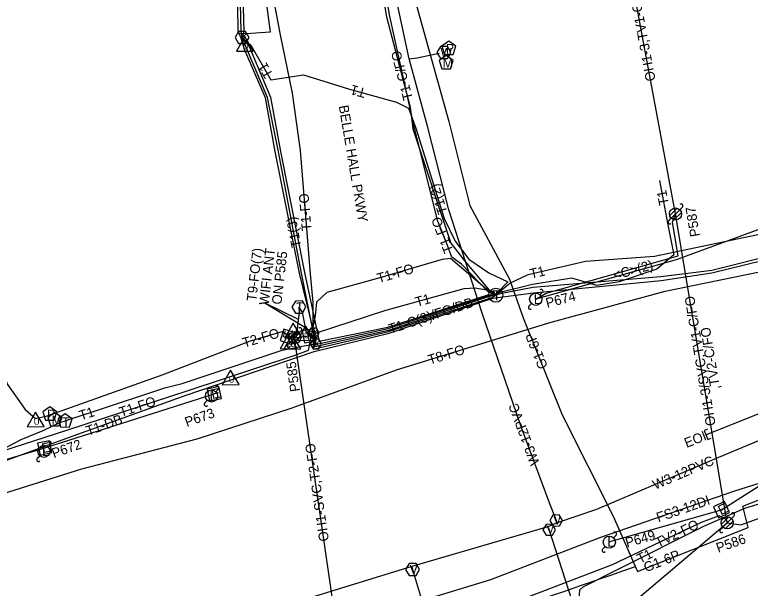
# Model space of a CAD drawing. Extents: x 2336688 to 2352634, y 362473 to 369571.
# Drawn here: x 2350284.9 to 2350587.4, y 368425.3 to 368661.2 of the extents above; entities that cross this region are included whole.
import ezdxf

# ---------------------------------------------------------------- set-up
doc = ezdxf.new("R2010")
doc.units = 0
for name, color, linetype in [('RD_EX_DV_Prop', 7, 'Continuous'), ('RD_EX_DV_TX_Prop', 7, 'Continuous'), ('RD_EX_RW', 7, 'Continuous'), ('RD_EX_RW_TX', 7, 'Continuous'), ('RD_HC_CL_Rel', 7, 'Continuous'), ('RD_HC_Data_Tic', 7, 'Continuous'), ('RD_PD_CstnLmt', 7, 'Continuous'), ('RD_PD_Final_TrvlWay', 7, 'Continuous'), ('RD_PD_PatLn2', 7, 'Continuous'), ('RD_PD_PatLn3', 7, 'Continuous'), ('RD_PD_PatLn4', 7, 'Continuous'), ('RD_SHT_ShtClip', 7, 'Continuous'), ('RD_Sketch1', 7, 'Continuous'), ('RD_Sketch2', 7, 'Continuous'), ('RD_Sketch5', 7, 'Continuous'), ('RD_TX_Misc1', 7, 'Continuous')]:
    doc.layers.add(name, color=color, linetype=linetype)

msp = doc.modelspace()

# ---------------------------------------------------------------- linework, layer by layer
at = {"layer": 'RD_EX_RW'}
for q in [(2350404.43, 368532.56), (2350401.5, 368535.99)]:
    msp.add_line((2350387.42, 368542.82), q, dxfattribs=at)
at = {"layer": 'RD_EX_RW_TX'}
for points in [[(2350388.75, 369009.97), (2350397.22, 368958.18), (2350404.87, 368909.74), (2350411.62, 368859.62), (2350417.85, 368811.58), (2350423.06, 368763.6), (2350429.71, 368713.05), (2350437.68, 368660.97), (2350447.52, 368623.27), (2350448.62, 368614.36), (2350464.25, 368567.26), (2350469.96, 368559.91), (2350480.07, 368547.98), (2350481.76, 368547.21), (2350482.64, 368545.94)], [(2350482.64, 368545.94), (2350481.31, 368546.91), (2350479.8, 368547.15), (2350468.6, 368558.68), (2350464.62, 368561.57), (2350462.94, 368566.31), (2350458.88, 368576.34), (2350449.26, 368614.59), (2350439.06, 368661.24), (2350430.47, 368713.16), (2350424.26, 368763.63), (2350419.63, 368812.07), (2350412.7, 368859.94), (2350405.88, 368909.92), (2350398.4, 368958.42), (2350390.1, 369010.31)], [(2350326.28, 369000.12), (2350332.79, 368954.21), (2350348.71, 368900.79), (2350357.27, 368854.35), (2350367.98, 368802.75), (2350376.91, 368753.55), (2350383.44, 368712.71), (2350383.88, 368703.63), (2350378.08, 368694.65), (2350379.09, 368654.23), (2350378.39, 368651.86), (2350381.3, 368648.18), (2350390.15, 368627.39), (2350394.17, 368604.93), (2350404.13, 368555.18), (2350410.09, 368526.92), (2350438.39, 368532.65), (2350479.49, 368546), (2350481.06, 368546.18), (2350482.64, 368545.94)], [(2350408.75, 368525.77), (2350408.57, 368526.1), (2350402.78, 368554.87), (2350393.43, 368604.85), (2350388.81, 368627.14), (2350380.28, 368647.53), (2350378.39, 368651.86), (2350378.01, 368654.34), (2350377.12, 368694.93), (2350382.9, 368704.01), (2350382.6, 368712.47), (2350374.83, 368753.42), (2350364.37, 368802.15), (2350353.94, 368853.94), (2350343.54, 368900.46), (2350334.62, 368932.93), (2350327.82, 368949.81), (2350315.54, 368963), (2350294.55, 368977.59)], [(2350171.87, 368427.87), (2350217.94, 368444.86), (2350264.95, 368459.5), (2350312.55, 368474.5), (2350359.96, 368486.74), (2350398.97, 368499.58), (2350441.96, 368515.14), (2350504.54, 368534.47), (2350552.41, 368547.56), (2350602.53, 368557.75), (2350651.32, 368575.57), (2350695.05, 368595.12), (2350743.66, 368609.85), (2350789.93, 368626.9), (2350839.13, 368641.87), (2350884.51, 368658.74), (2350931.21, 368675.96), (2350977.7, 368689.48), (2351026.67, 368705.73), (2351072.69, 368726.31)], [(2350550.06, 368593.04), (2350553.4, 368575.51), (2350556.04, 368562.41), (2350549.03, 368556.57), (2350533.44, 368551.33), (2350524.3, 368549.87), (2350514.04, 368552.9), (2350497.9, 368550.25), (2350484.03, 368546.87), (2350482.64, 368545.94), (2350481.02, 368545.5), (2350479.63, 368545.14), (2350438.63, 368531.39), (2350408.36, 368524.65), (2350407.99, 368526.73), (2350407.79, 368529.35), (2350407.84, 368530.28), (2350407.93, 368530.85), (2350401.96, 368554.87), (2350391.98, 368604.93), (2350387.98, 368627), (2350379.43, 368646.93), (2350378.07, 368651.64), (2350376.74, 368654.45), (2350376.28, 368695.46)], [(2350386.33, 368681.11), (2350389.94, 368654.04), (2350380.03, 368653.44), (2350378.39, 368651.86), (2350382.02, 368648.71), (2350390.17, 368634.44), (2350403.61, 368636.52), (2350422.61, 368630.68), (2350441.9, 368625.3), (2350446.8, 368622.86), (2350449.89, 368614.63), (2350461.49, 368577.44), (2350466.02, 368568.14), (2350471.7, 368560.62), (2350479.9, 368555.07), (2350487.67, 368551.3), (2350483.53, 368547.05), (2350482.64, 368545.94)], [(2350388.65, 368681.34), (2350394.12, 368653.01), (2350399.06, 368628.98), (2350402.27, 368605.42), (2350406.43, 368554.68), (2350407.49, 368542.86), (2350407.54, 368537.76), (2350407.61, 368523.66), (2350438.65, 368530.88), (2350479.91, 368544.49), (2350481.3, 368544.93), (2350482.64, 368545.94)], [(2350275.43, 368480.16), (2350287.53, 368486.53), (2350296.58, 368490.27), (2350303.41, 368493.47), (2350305.37, 368494.05), (2350307.12, 368494.79), (2350317.72, 368498.2), (2350346.6, 368507.79), (2350353.81, 368509.54), (2350394.92, 368523.3), (2350407.49, 368525.69), (2350408.75, 368525.77), (2350410.33, 368525.94), (2350438.45, 368532.21), (2350479.57, 368545.7), (2350481.03, 368545.75), (2350482.64, 368545.94), (2350483.89, 368546.96), (2350488.5, 368550.84), (2350496.07, 368554.39), (2350519.66, 368559.91), (2350547.98, 368561.97), (2350596.49, 368572.11)], [(2350078.43, 368410.11), (2350121.57, 368423.4), (2350143.91, 368430.19), (2350168.83, 368437.37), (2350214.23, 368453.99), (2350261.28, 368470.53), (2350307.48, 368487.5), (2350354.97, 368504.62), (2350408.06, 368522.73), (2350438.94, 368530.22), (2350481.48, 368544.67), (2350498.27, 368546.89), (2350550.8, 368551.91), (2350571.6, 368555.09), (2350599.59, 368561.91)], [(2350599.46, 368563.03), (2350571.6, 368556.05), (2350550.59, 368553.36), (2350498.04, 368549.07), (2350484.48, 368546.36), (2350482.64, 368545.94), (2350481.12, 368546.45), (2350467.8, 368557.82), (2350464.13, 368560.91), (2350460.65, 368560.51), (2350435.07, 368553), (2350413.22, 368546.93), (2350409.03, 368543.01), (2350408.48, 368537.37), (2350405.62, 368523.15), (2350399.7, 368520.91), (2350356.09, 368506.55), (2350306.59, 368490.37), (2350279.1, 368481.38), (2350264.89, 368477.05), (2350263.31, 368482.45), (2350263.08, 368483.91)], [(2350482.64, 368545.94), (2350481.66, 368546.86), (2350479.7, 368547.74), (2350474.3, 368548.82), (2350469.57, 368548.46), (2350437, 368539.4), (2350408.92, 368530.22), (2350407.84, 368530.28)], [(2350272, 368534.04), (2350281.85, 368509.07), (2350289.13, 368498.91), (2350293.42, 368495.17), (2350298.29, 368496.27), (2350346, 368513.18), (2350381.9, 368527.1), (2350394.9, 368530.89), (2350398.81, 368528.45), (2350399.92, 368528.37), (2350406.03, 368529.13), (2350404.87, 368530.3), (2350403.18, 368538.96), (2350401.8, 368540.99), (2350401.84, 368538.95), (2350400.7, 368528.92), (2350400.64, 368528.58), (2350399.92, 368528.37)], [(2350438.31, 368353.14), (2350443.06, 368361.29), (2350461.37, 368365.85), (2350472.57, 368367.45), (2350475.55, 368368.48), (2350473.81, 368381.16), (2350466.45, 368400.79), (2350465.63, 368402.3), (2350467.73, 368402.72), (2350477.74, 368405.85), (2350509.1, 368415.22), (2350517.8, 368417.58), (2350517.14, 368422.45), (2350517.32, 368424.65), (2350518.71, 368425.94), (2350533.4, 368433.24), (2350568.35, 368450.8), (2350585.17, 368458.19), (2350631.55, 368472.55)], [(2350577.9, 368452.24), (2350577.71, 368453.44), (2350574.65, 368455.11), (2350567.18, 368452.41), (2350530.66, 368434.99), (2350490.17, 368419.45), (2350440.7, 368401.32), (2350389.67, 368387.65), (2350345.03, 368375.16), (2350304.59, 368361.14), (2350291.95, 368359.89), (2350248.07, 368344.34), (2350203.54, 368331.65), (2350161.47, 368317.74), (2350118.87, 368303.47)]]:
    msp.add_lwpolyline(points, dxfattribs=at)
for points in [[(2350381.28, 368651.86), (2350379.83, 368654.36), (2350376.95, 368654.36), (2350375.5, 368651.86), (2350376.95, 368649.36), (2350379.83, 368649.36)], [(2350404.68, 368541.03), (2350403.21, 368543.51), (2350400.32, 368543.47), (2350398.91, 368540.95), (2350400.39, 368538.47), (2350403.27, 368538.51)], [(2350408.05, 368532.04), (2350403.13, 368531.15), (2350404.01, 368526.23), (2350408.93, 368527.11)], [(2350410.14, 368530.28), (2350408.99, 368532.28), (2350406.68, 368532.28), (2350405.53, 368530.28), (2350406.68, 368528.28), (2350408.99, 368528.28)], [(2350411.06, 368525.77), (2350409.91, 368527.77), (2350407.6, 368527.77), (2350406.44, 368525.77), (2350407.6, 368523.77), (2350409.91, 368523.77)], [(2350305.6, 368497.08), (2350302.78, 368494.96), (2350303.91, 368491.63), (2350307.44, 368491.67), (2350308.48, 368495.04)]]:
    msp.add_lwpolyline(points, close=True, dxfattribs=at)
msp.add_circle((2350482.74, 368545.84), 2.89, dxfattribs=at)
at = {"layer": 'RD_HC_CL_Rel'}
msp.add_lwpolyline([(2350393.46, 369009.48), (2350402.47, 368959.36), (2350407.9, 368910.71), (2350415.61, 368860.55), (2350423.26, 368811.96), (2350431.46, 368765.12), (2350440.2, 368714.98), (2350450.17, 368665.06), (2350463.37, 368617.29), (2350472.09, 368582.73), (2350488.34, 368552.4), (2350494.02, 368536.52), (2350510.05, 368496.62), (2350530.98, 368454.93), (2350541.05, 368432.24), (2350586.57, 368450.28), (2350584.33, 368459.13), (2350630.35, 368477.17)], dxfattribs=at)
msp.add_open_spline([(2350361.36, 368372.49), (2350363.93, 368373.39), (2350366.51, 368374.3), (2350381.17, 368379.43), (2350395.35, 368384.35), (2350403.79, 368387.84), (2350418.76, 368392.43), (2350425.89, 368394.88), (2350436.61, 368398.57), (2350440.18, 368399.8), (2350445.54, 368401.64), (2350447.33, 368402.26), (2350450.91, 368403.49), (2350452.7, 368404.1), (2350483.05, 368414.54), (2350511.62, 368424.37), (2350540.18, 368434.2)], degree=3, dxfattribs=at)
at = {"layer": 'RD_HC_Data_Tic'}
for p, q in [((2350554.27, 368578.62), (2350557.33, 368581.68)), ((2350554.92, 368577.5), (2350558.45, 368581.03)), ((2350556.04, 368576.85), (2350559.1, 368579.91)), ((2350558.45, 368581.03), (2350559.51, 368582.1)), ((2350553.86, 368576.44), (2350554.92, 368577.5)), ((2350500.93, 368545.98), (2350501.98, 368547.05)), ((2350496.38, 368541.33), (2350497.43, 368542.4)), ((2350397.51, 368527.72), (2350400.57, 368530.78)), ((2350398.16, 368526.6), (2350401.69, 368530.14)), ((2350399.28, 368525.96), (2350402.34, 368529.02)), ((2350401.69, 368530.14), (2350402.75, 368531.2)), ((2350397.1, 368525.54), (2350398.16, 368526.6)), ((2350367.58, 368506.17), (2350368.63, 368507.24)), ((2350363.04, 368501.53), (2350364.08, 368502.6)), ((2350298.66, 368483.4), (2350299.71, 368484.47)), ((2350294.11, 368478.76), (2350295.16, 368479.83)), ((2350575.49, 368451.6), (2350578.55, 368454.66)), ((2350576.14, 368450.48), (2350579.67, 368454.01)), ((2350577.26, 368449.83), (2350580.32, 368452.89)), ((2350579.67, 368454.01), (2350580.73, 368455.07)), ((2350575.07, 368449.42), (2350576.14, 368450.48)), ((2350531.18, 368446.08), (2350532.23, 368447.15)), ((2350526.63, 368441.43), (2350527.68, 368442.5))]:
    msp.add_line(p, q, dxfattribs=at)
for centre in [(2350556.68, 368579.27), (2350499.18, 368544.19), (2350399.92, 368528.37), (2350365.83, 368504.39), (2350296.91, 368481.62), (2350577.9, 368452.24), (2350529.43, 368444.29)]:
    msp.add_circle(centre, 2.5, dxfattribs=at)
for centre, start, end in [((2350558.98, 368582.63), 315, 135), ((2350554.39, 368575.91), 135, 315), ((2350501.44, 368547.57), 315.5955, 135.5955), ((2350496.91, 368540.81), 135.5955, 315.5955), ((2350402.22, 368531.73), 315, 135), ((2350397.63, 368525.01), 135, 315), ((2350368.1, 368507.77), 315.5955, 135.5955), ((2350363.57, 368501), 135.5955, 315.5955), ((2350299.18, 368485), 315.5955, 135.5955), ((2350294.65, 368478.23), 135.5955, 315.5955), ((2350580.2, 368455.6), 315, 135), ((2350531.69, 368447.67), 315.5955, 135.5955), ((2350575.6, 368448.89), 135, 315), ((2350527.16, 368440.91), 135.5955, 315.5955)]:
    msp.add_arc(centre, 0.75, start, end, dxfattribs=at)
at = {"layer": 'RD_PD_Final_TrvlWay'}
for points in [[(2351152.66, 368771.86), (2351150.34, 368773.72), (2351066.03, 368744.69), (2351065.02, 368741.68), (2351062.36, 368743.39), (2350925.92, 368693.73), (2350924.59, 368690.57), (2350921.77, 368692.25), (2350823.59, 368658.07), (2350823.45, 368655.36), (2350821.04, 368657.17), (2350712.58, 368618.54), (2350712.43, 368615.82), (2350710.28, 368617.73), (2350612.32, 368583.41), (2350611.09, 368580.31), (2350556.98, 368560.45), (2350499.18, 368544.19), (2350503.41, 368546.65), (2350527.75, 368553.5), (2350557.82, 368562.03), (2350555.37, 368575.95), (2350556.68, 368579.27)], [(2350097.74, 368416.86), (2350230.94, 368463.23), (2350297.22, 368483.05), (2350366.95, 368505.3)], [(2350529.28, 368444.39), (2350575.55, 368457.63), (2350639.85, 368498.52)]]:
    msp.add_lwpolyline(points, dxfattribs=at)
for points in [[(2350395.63, 368531.93), (2350394.06, 368527.18), (2350398.8, 368525.6), (2350400.38, 368530.35)], [(2350368.88, 368508.26), (2350363.99, 368507.24), (2350365.01, 368502.34), (2350369.91, 368503.37)], [(2350299.14, 368486.02), (2350294.25, 368484.97), (2350295.3, 368480.08), (2350300.19, 368481.14)], [(2350576.75, 368460.95), (2350572.23, 368458.82), (2350574.36, 368454.3), (2350578.88, 368456.43)]]:
    msp.add_lwpolyline(points, close=True, dxfattribs=at)
at = {"layer": 'RD_PD_PatLn3'}
for points in [[(2350379.53, 368652.25), (2350376.07, 368646.25), (2350382.99, 368646.25)], [(2350399.4, 368534.35), (2350396.02, 368528.3), (2350402.95, 368528.4)], [(2350404.55, 368533.3), (2350401.16, 368527.26), (2350408.09, 368527.35)], [(2350397.49, 368529.88), (2350394.11, 368523.83), (2350401.03, 368523.93)], [(2350398.98, 368529.71), (2350395.6, 368523.66), (2350402.53, 368523.76)], [(2350373.61, 368515.09), (2350370.23, 368509.05), (2350377.16, 368509.14)], [(2350293.45, 368497.76), (2350290.06, 368491.72), (2350296.99, 368491.81)]]:
    msp.add_lwpolyline(points, close=True, dxfattribs=at)
for points in [[(2350569.2, 368488.37), (2350617.02, 368507.64), (2350668.18, 368527.03), (2350714.72, 368541.98), (2350754.57, 368558.07), (2350804.34, 368574.84), (2350847.72, 368593.34)], [(2350569.84, 368490.78), (2350568.45, 368490.22), (2350569.95, 368486.51), (2350571.34, 368487.07)]]:
    msp.add_lwpolyline(points, dxfattribs=at)
at = {"layer": 'RD_SHT_ShtClip'}
for p, q in [((2350556.68, 368579.27), (2350524.13, 368754.58)), ((2350577.9, 368452.24), (2350556.68, 368579.27)), ((2350419.25, 368396.14), (2350399.92, 368528.37))]:
    msp.add_line(p, q, dxfattribs=at)
for points in [[(2350577.9, 368452.24), (2350583.51, 368451.44), (2350635.64, 368470.23), (2350639.45, 368474.42)], [(2350419.25, 368396.14), (2350467.37, 368395.02), (2350541.18, 368421.12), (2350577.9, 368452.24)]]:
    msp.add_lwpolyline(points, dxfattribs=at)
at = {"layer": 'RD_Sketch2'}
for points in [[(2350508, 368452.18), (2350507.59, 368453.47), (2350504.92, 368459.98), (2350493.07, 368492.16), (2350477.05, 368538.83), (2350463.38, 368580.99), (2350454.69, 368615.46), (2350447.11, 368643.06), (2350441.53, 368669.46), (2350433.16, 368714.57), (2350423.37, 368764.37), (2350416.37, 368810.41), (2350407.58, 368858.95), (2350400.55, 368906.55), (2350395.74, 368941.34), (2350393.27, 368957.78), (2350385.2, 369007.61)], [(2351042.86, 368655.18), (2350995.25, 368636.19), (2350951.94, 368625.72), (2350904.41, 368609.66), (2350850.2, 368589.13), (2350807.88, 368571.45), (2350758.45, 368549.2), (2350717.62, 368531.89), (2350669.89, 368513.41), (2350618.71, 368497.66), (2350574.37, 368479.11), (2350524.2, 368457.7), (2350508, 368452.18), (2350504.2, 368450.53), (2350448.23, 368434.31), (2350382.35, 368413.96), (2350336.49, 368399.02), (2350285.67, 368383.39), (2350239.06, 368369.9), (2350196.44, 368356.53), (2350109.57, 368328)], [(2350447.11, 368643.06), (2350450.45, 368643.54), (2350459.42, 368645.41)], [(2350504.2, 368450.53), (2350504.56, 368449.6), (2350516.6, 368412.18), (2350531.6, 368361.22)], [(2350448.23, 368434.31), (2350448.51, 368433), (2350453.38, 368416.62), (2350451.15, 368413.25), (2350448.63, 368408.6)]]:
    msp.add_lwpolyline(points, dxfattribs=at)
for points in [[(2350463.39, 368650.41), (2350460.49, 368648.3), (2350461.6, 368644.89), (2350465.18, 368644.89), (2350466.29, 368648.3)], [(2350464.28, 368645.69), (2350462.84, 368648.19), (2350459.95, 368648.19), (2350458.51, 368645.69), (2350459.95, 368643.19), (2350462.84, 368643.19)], [(2350462.32, 368644.47), (2350459.42, 368642.36), (2350460.52, 368638.95), (2350464.11, 368638.95), (2350465.22, 368642.36)], [(2350299.3, 368499.96), (2350296.42, 368497.83), (2350297.56, 368494.43), (2350301.15, 368494.46), (2350302.22, 368497.88)], [(2350301.37, 368497.67), (2350298.49, 368495.53), (2350299.65, 368492.13), (2350303.23, 368492.18), (2350304.29, 368495.61)], [(2350510.19, 368453.22), (2350508.86, 368455.45), (2350506.26, 368455.41), (2350504.99, 368453.15), (2350506.32, 368450.91), (2350508.92, 368450.95)], [(2350507.35, 368449.39), (2350506.02, 368451.62), (2350503.42, 368451.59), (2350502.15, 368449.32), (2350503.48, 368447.09), (2350506.08, 368447.12)], [(2350451.39, 368433), (2350449.95, 368435.5), (2350447.06, 368435.5), (2350445.62, 368433), (2350447.06, 368430.5), (2350449.95, 368430.5)]]:
    msp.add_lwpolyline(points, close=True, dxfattribs=at)
at = {"layer": 'RD_Sketch5'}
msp.add_lwpolyline([(2350116.54, 368309.62), (2350157.85, 368325.74), (2350201.04, 368338.25), (2350246.21, 368351.09), (2350290.88, 368366.1), (2350342.68, 368382.19), (2350386.37, 368397.34), (2350435.33, 368415.03), (2350480.68, 368428.89), (2350526.02, 368446.27), (2350580.59, 368465.31), (2350628.33, 368480.35), (2350681.49, 368498.77), (2350722.35, 368517.44), (2350762.63, 368535.33), (2350810.28, 368554.98), (2350857.34, 368575.64), (2350905.94, 368596.06), (2350950.65, 368611.89), (2350997.52, 368629.24), (2351044.06, 368648.74)], dxfattribs=at)

# ---------------------------------------------------------------- texts
at = {"layer": 'RD_EX_DV_Prop'}
msp.add_text('<C>(2)', height=4, rotation=15.7126, dxfattribs=at).set_placement((2350531.75, 368552.1))
at = {"layer": 'RD_EX_DV_TX_Prop'}
for s, rotation, p in [('P587', 99.4837, (2350566.75, 368570.23)), ('P674', 14.5198, (2350503.87, 368540.64)), ('P585', 98.3135, (2350402.23, 368506.45)), ('P673', 19.3428, (2350355.68, 368491.63)), ('P672', 19.3428, (2350300.96, 368478.8)), ('P649', 15.9665, (2350536.71, 368442.01)), ('P586', 19.4748, (2350574.23, 368439.87))]:
    msp.add_text(s, height=4, rotation=rotation, dxfattribs=at).set_placement(p)
at = {"layer": 'RD_EX_RW'}
for s, rotation, p in [('T1-C/FO', 104.629, (2350448.7, 368626.67)), ('T1', 119.7384, (2350391.35, 368636.56)), ('T1', 164.4122, (2350429.7, 368630.78)), ('T1(2)', 107.3234, (2350462.94, 368579.88)), ('T1', 100.8212, (2350553.96, 368583.27)), ('T1-FO', 94.6896, (2350406.98, 368572.51)), ('T1(3)', 100.5935, (2350402.77, 368565.8)), ('T1-FO', 111.2181, (2350465.41, 368564.11)), ('T9-FO(7)', 83.5229, (2350384.23, 368543.21)), ('WIFI ANT', 83.5229, (2350389.3, 368541.65)), ('ON P585', 83.5229, (2350394.56, 368541.86)), ('T1-FO', 16.3672, (2350434.58, 368550.77)), ('T1', 13.1643, (2350497.26, 368552.62)), ('T1-C(3)/FO/DB', 18.1536, (2350439.42, 368529.93)), ('T1', 15.5486, (2350450.28, 368541.02)), ('T2-FO', 16.2385, (2350379.23, 368524.24)), ('T8-FO', 17.1639, (2350455.6, 368517.26)), ('T1-FO', 18.0981, (2350328.62, 368495.76)), ('T1', 17.8408, (2350312.11, 368494.3)), ('T1-DB', 19.8276, (2350315.07, 368487.99)), ('TV2-FO', 25.4928, (2350549.5, 368441.97)), ('T1', 26.6797, (2350542.07, 368435.36))]:
    msp.add_text(s, height=4, rotation=rotation, dxfattribs=at).set_placement(p)
at = {"layer": 'RD_EX_RW_TX'}
for s, height, p in [('T', 3.75, (2350377.18, 368649.99)), ('X', 3, (2350406.89, 368528.78)), ('X', 3, (2350407.81, 368524.27))]:
    msp.add_text(s, height=height, dxfattribs=at).set_placement(p)
for s, height, rotation, p in [('T', 4.12, 0.7793, (2350481.43, 368543.76)), ('T', 3.75, 0.7793, (2350400.61, 368539.1)), ('F', 4, 10.1596, (2350405.26, 368526.97)), ('T', 3.75, 0.7793, (2350304.45, 368491.83))]:
    msp.add_text(s, height=height, rotation=rotation, dxfattribs=at).set_placement(p)
at = {"layer": 'RD_HC_Data_Tic'}
for p in [(2350498.39, 368542.25), (2350365.04, 368502.44), (2350296.12, 368479.67), (2350528.64, 368442.35)]:
    msp.add_text('L', height=4, rotation=0.5955, dxfattribs=at).set_placement(p)
at = {"layer": 'RD_PD_CstnLmt'}
for rotation, p in [(110.2275, (2350500.87, 368476.76)), (23.1171, (2350548.3, 368465.81))]:
    msp.add_text('W3-12PVC', height=4, rotation=rotation, dxfattribs=at).set_placement(p)
at = {"layer": 'RD_PD_Final_TrvlWay'}
for rotation, p in [(71.5861, (2350398.73, 368526.98)), (11.7989, (2350366.17, 368503.1)), (12.1485, (2350296.45, 368480.84)), (25.258, (2350575.31, 368455.3))]:
    msp.add_text('E', height=4, rotation=rotation, dxfattribs=at).set_placement(p)
at = {"layer": 'RD_PD_PatLn2'}
for rotation, p in [(111.8779, (2350504.24, 368516.46)), (21.6182, (2350544.53, 368431.83))]:
    msp.add_text('G1-6P', height=4, rotation=rotation, dxfattribs=at).set_placement(p)
at = {"layer": 'RD_PD_PatLn3'}
msp.add_text('U', height=2.4, dxfattribs=at).set_placement((2350378.77, 368647.05))
for s, height, rotation, p in [('U', 2.4, 0.7793, (2350398.72, 368529.14)), ('U', 2.4, 0.7793, (2350403.86, 368528.09)), ('U', 2.4, 0.7793, (2350396.8, 368524.67)), ('U', 2.4, 0.7793, (2350398.3, 368524.5)), ('U', 2.4, 0.7793, (2350372.93, 368509.88)), ('U', 2.4, 0.7793, (2350292.76, 368492.55)), ('EOI', 4, 21.9479, (2350561.26, 368483.01))]:
    msp.add_text(s, height=height, rotation=rotation, dxfattribs=at).set_placement(p)
at = {"layer": 'RD_PD_PatLn4'}
for s, rotation, p in [('OH1-3,TV1-C/FO,TV2-C/FO', 100.5193, (2350548.51, 368634.24)), ('OH1-3/SVC,TV1-C/FO', 99.4837, (2350573.22, 368492.43)), (',TV2-C/FO', 99.4837, (2350575.05, 368507.45)), ('OH1-SVC,T2-FO', 98.3135, (2350414.15, 368444.87))]:
    msp.add_text(s, height=4, rotation=rotation, dxfattribs=at).set_placement(p)
at = {"layer": 'RD_Sketch1'}
msp.add_text('FS3-12DI', height=4, rotation=19.2332, dxfattribs=at).set_placement((2350549.63, 368452.39))
at = {"layer": 'RD_Sketch2'}
for s, p in [('W', (2350460.01, 368643.81)), ('M', (2350460.95, 368639.43)), ('V', (2350447.3, 368431.12))]:
    msp.add_text(s, height=3.75, dxfattribs=at).set_placement(p)
for s, height, rotation, p in [('P', 3.75, 360, (2350462.24, 368645.48)), ('P', 3.75, 0.5629, (2350298.2, 368495.03)), ('M', 3.75, 0.7793, (2350300.06, 368492.61)), ('V', 3.38, 0.7793, (2350506.52, 368451.48)), ('V', 3.38, 0.7793, (2350503.68, 368447.65))]:
    msp.add_text(s, height=height, rotation=rotation, dxfattribs=at).set_placement(p)
at = {"layer": 'RD_TX_Misc1'}
msp.add_text('BELLE HALL PKWY', height=4, rotation=279.6033, dxfattribs=at).set_placement((2350418.13, 368623.71))

doc.saveas('drawing.dxf')
